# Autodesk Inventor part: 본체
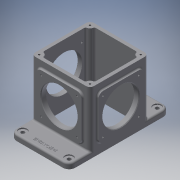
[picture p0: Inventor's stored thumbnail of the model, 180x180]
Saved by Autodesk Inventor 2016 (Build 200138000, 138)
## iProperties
Created: 2018-09
Part Number: 본체
Material: 알루미늄 6061
Document SubType Name: Modeling
Designer: mduedu
Density: 2.71 g/cm^3
Appearance: 기본값
Mass: 879.979 g
Surface Area: 940.033 cm^2
Volume: 324.716 cm^3
Author: mduedu
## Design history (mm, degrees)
sketch "스케치1"
  geometry: L1 (90, 52.5)-(-90, 52.5); L2 (-90, 52.5)-(-90, -52.5); L3 (-90, -52.5)-(90, -52.5); L4 (90, -52.5)-(90, 52.5); L5 (90, 52.5)-(-90, -52.5); L6 (-90, 52.5)-(90, -52.5); 1 further point
  constraints: 12 end point, 2 midpoint, 2 parallel, 1 horizontal, 1 perpendicular
  dimensions: "d0" = 180 distance of L3.end L2.end; "d1" = 105 distance of L2.end L1.end
extrude "돌출1" new body sketch "스케치1" distance "d2" = 10; taper "d3" = 0 deg
sketch "스케치2"
  geometry: L1 (-52.5, -52.5)-(52.5, -52.5); L2 (52.5, -52.5)-(52.5, 52.5); L3 (52.5, 52.5)-(-52.5, 52.5); L4 (-52.5, 52.5)-(-52.5, -52.5); L5 (-52.5, -52.5)-(52.5, 52.5); L6 (52.5, -52.5)-(-52.5, 52.5); 1 further point
  constraints: 12 end point, 2 midpoint, 2 parallel, 1 horizontal, 1 perpendicular
  dimensions: "d4" = 105 distance of L3.end L2.end; "d5" = 105 distance of L2.end L1.end
extrude "돌출2" join sketch "스케치2" distance "d6" = 100; taper "d7" = 0 deg
sketch "스케치14"
  geometry: L1 (-52.5, 52.5)-(52.5, 52.5) reference; L2 (52.5, 52.5)-(52.5, -52.5) reference; L3 (52.5, -52.5)-(-52.5, -52.5) reference; L4 (-52.5, -52.5)-(-52.5, 52.5) reference; L5 (46.5, 46.5)-(-46.5, 46.5); L6 (-46.5, 46.5)-(-46.5, -46.5); L7 (-46.5, -46.5)-(46.5, -46.5); L8 (46.5, -46.5)-(46.5, 46.5); 1 further point
  constraints: 8 end point, 3 other
  dimensions: "d85" = 6 distance between parallel lines of L5 L1
extrude "돌출10" cut sketch "스케치14" stored distance "d86" = 10; taper "d87" = 0 deg
fillet "모깎기1" dims "d12" = 7
sketch "스케치15"
  geometry: A1 r 7 centre (-45.5, 45.5) between (-45.5, 52.5) and (-52.5, 45.5) reference; A2 r 7 centre (45.5, 45.5) between (52.5, 45.5) and (45.5, 52.5) reference; A3 r 7 centre (45.5, -45.5) between (45.5, -52.5) and (52.5, -45.5) reference; A4 r 7 centre (-45.5, -45.5) between (-52.5, -45.5) and (-45.5, -52.5) reference; 5 further points
  constraints: 4 coincident, 4 vertical alignment, 8 other
extrude "돌출11" join sketch "스케치15" stored distance "d88" = 10; taper "d89" = 0 deg
fillet "모깎기15" dims "d90" = 3
sketch "스케치6"
  geometry: L1 (50, 17.5)-(130, 17.5); L2 (130, 17.5)-(130, 97.5); L3 (130, 97.5)-(50, 97.5); L4 (50, 97.5)-(50, 17.5); L5 (50, 17.5)-(130, 97.5); L6 (130, 17.5)-(50, 97.5); L7 (0, 0)-(180, 0) reference; 4 further points
  constraints: 12 end point, 4 midpoint, 2 parallel, 1 horizontal, 1 perpendicular, 1 vertical alignment
  dimensions: "d25" = 80 distance of L3.end L2.end; "d26" = 80 distance of L2.end L1.end; "d27" = 57.5 distance of point (90, 0) point (90, 57.5)
extrude "돌출6" join sketch "스케치6" distance "d28" = 3; taper "d29" = 0 deg
fillet "모깎기7" dims "d30" = 8
sketch "스케치7"
  geometry: C1 r 32.5 at (90, 57.5); 1 further point
  constraints: 1 centre point, 1 vertical alignment
  dimensions: "d32" = 65 diameter of C1; "d33" = 57.5 distance of C1.centre point (90, 0)
extrude "돌출7" cut sketch "스케치7" stored distance "d34" = 3; taper "d35" = 0 deg
fillet "모깎기9" dims "d36" = 3
sketch "스케치8"
  geometry: L1 (5.5, 7.5)-(85.5, 7.5); L2 (85.5, 7.5)-(85.5, 87.5); L3 (85.5, 87.5)-(5.5, 87.5); L4 (5.5, 87.5)-(5.5, 7.5); L5 (5.5, 7.5)-(85.5, 87.5); L6 (85.5, 7.5)-(5.5, 87.5); L7 (-7, -10)-(98, -10) reference; C1 r 32.5 at (45.5, 47.5); 4 further points
  constraints: 12 end point, 4 midpoint, 2 parallel, 1 centre point, 1 coincident, 1 horizontal, 1 perpendicular, 1 vertical alignment
  dimensions: "d37" = 80 distance of L3.end L2.end; "d38" = 80 distance of L2.end L1.end; "d39" = 57.5 distance from line of point (45.5, 47.5) L7; "d40" = 65 diameter of C1
extrude "돌출8" join sketch "스케치8" distance "d41" = 3; taper "d42" = 0 deg
fillet "모깎기10" dims "d43" = 8
extrude "돌출9" cut sketch "스케치8" stored distance "d44" = 3; taper "d45" = 0 deg
fillet "모깎기11" dims "d46" = 3
sketch "스케치9"
  geometry: L1 (50, 89.5)-(50, 25.5) reference; L2 (58, 17.5)-(122, 17.5) reference; L3 (130, 25.5)-(130, 89.5) reference; L4 (122, 97.5)-(58, 97.5) reference; C1 r 32.5 at (90, 57.5) reference; A1 r 8 centre (58, 89.5) between (58, 97.5) and (50, 89.5) reference; A2 r 8 centre (58, 25.5) between (50, 25.5) and (58, 17.5) reference; A3 r 8 centre (122, 25.5) between (122, 17.5) and (130, 25.5) reference; A4 r 8 centre (122, 89.5) between (130, 89.5) and (122, 97.5) reference; 5 further points
  constraints: 4 coincident
hole "구멍1" sketch "스케치9" at (58, 89.5), (122, 89.5), (122, 25.5), (58, 25.5) diameter "d47" = 3.242; stored, may be unused: countersink angle "d51" = 90 deg, drill point angle "d53" = 118 deg; dims "d48" = 6, "d49" = 4, "d50" = 2, "d52" = 9
sketch "스케치10" dims "d30" = 8
  geometry: L1 (13.5, 7.5)-(77.5, 7.5) reference; L2 (85.5, 15.5)-(85.5, 79.5) reference; L3 (77.5, 87.5)-(13.5, 87.5) reference; L4 (5.5, 79.5)-(5.5, 15.5) reference; C1 r 32.5 at (45.5, 47.5) reference; A1 r 8 centre (13.5, 15.5) between (5.5, 15.5) and (13.5, 7.5) reference; A2 r 8 centre (77.5, 15.5) between (77.5, 7.5) and (85.5, 15.5) reference; A3 r 8 centre (77.5, 79.5) between (85.5, 79.5) and (77.5, 87.5) reference; A4 r 8 centre (13.5, 79.5) between (13.5, 87.5) and (5.5, 79.5) reference; 5 further points
  constraints: 4 coincident
hole "구멍2" sketch "스케치10" at (13.5, 79.5), (77.5, 79.5), (77.5, 15.5), (13.5, 15.5) diameter "d54" = 3.242; stored, may be unused: countersink angle "d58" = 90 deg, drill point angle "d60" = 118 deg; dims "d30" = 8, "d55" = 6, "d56" = 4, "d57" = 2, "d59" = 9
fillet "모깎기12" dims "d68" = 11
sketch "스케치16"
  geometry: A1 r 11 centre (-79, 41.5) between (-79, 52.5) and (-90, 41.5) reference; A2 r 11 centre (-79, -41.5) between (-90, -41.5) and (-79, -52.5) reference; A3 r 11 centre (79, 41.5) between (90, 41.5) and (79, 52.5) reference; A4 r 11 centre (79, -41.5) between (79, -52.5) and (90, -41.5) reference; 5 further points
  constraints: 4 coincident
hole "구멍5" sketch "스케치16" at (-79, 41.5), (79, 41.5), (79, -41.5), (-79, -41.5) diameter "d91" = 6.6; stored, may be unused: countersink angle "d95" = 90 deg, drill point angle "d97" = 118 deg; dims "d92" = 6, "d93" = 15, "d94" = 2, "d96" = 8
fillet "모깎기13" dims "d77" = 3
fillet "모깎기14" dims "d78" = 3
chamfer "모따기1" distance "d79" = 1; stored, may be unused: second distance "d80" = 2, angle "d81" = 45 deg
sketch "스케치17"
  geometry: A1 r 7 centre (-45.5, 45.5) between (-45.5, 52.5) and (-52.5, 45.5) reference; A2 r 7 centre (-45.5, -45.5) between (-52.5, -45.5) and (-45.5, -52.5) reference; A3 r 7 centre (45.5, -45.5) between (45.5, -52.5) and (52.5, -45.5) reference; A4 r 7 centre (45.5, 45.5) between (52.5, 45.5) and (45.5, 52.5) reference; 5 further points
  constraints: 4 coincident
hole "구멍6" sketch "스케치17" at (-45.5, 45.5), (45.5, 45.5), (45.5, -45.5), (-45.5, -45.5) diameter "d98" = 3.242; stored, may be unused: countersink angle "d102" = 90 deg, drill point angle "d104" = 118 deg; dims "d99" = 8, "d100" = 15, "d101" = 2, "d103" = 10
sketch "스케치13"
  geometry: L1 (90, -41.5)-(90, 41.5) reference; 2 further points
  constraints: 1 horizontal alignment, 1 other
  dimensions: "d82" = 10 distance from line of point (80, 0) L1
feature "엠보싱1" sketch "스케치13" dims "d0" = 180, "d1" = 105, "d25" = 80, "d26" = 80, "d27" = 57.5, "d83" = 0.5, "d84" = 0
node "솔리드1"
mirror "대칭1"
mirror "대칭2"
node "투영된 루프2"
node "투영된 루프3"
node "투영된 루프6"
